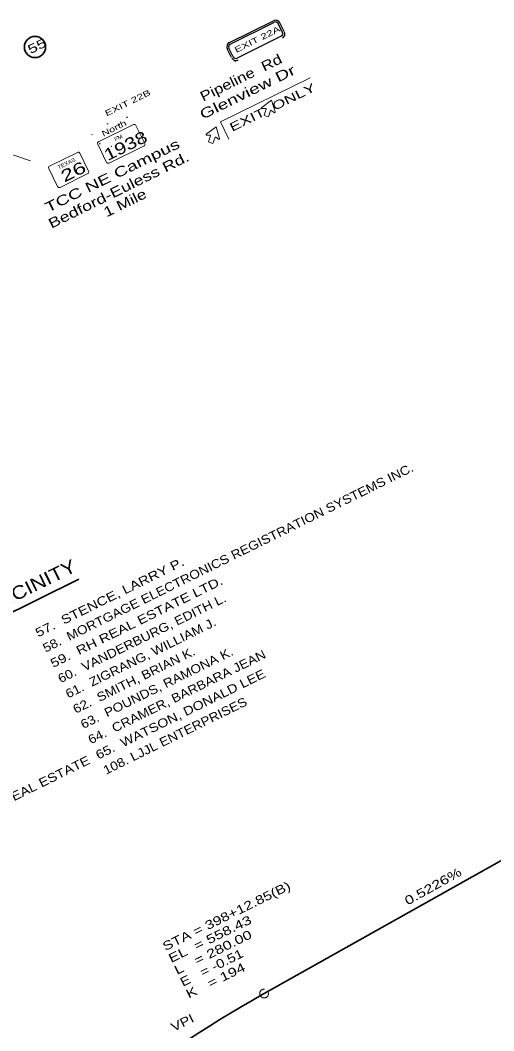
# Model space of a CAD drawing. Extents: x 2356431 to 2371438, y 6972864 to 6982525.
# Drawn here: x 2368116 to 2368867, y 6978894 to 6980496 of the extents above; entities that cross this region are included whole.
import ezdxf
from ezdxf.enums import TextEntityAlignment as Align

# ---------------------------------------------------------------- set-up
doc = ezdxf.new("R2010")
doc.units = 0
doc.header["$LTSCALE"] = 5.6
doc.linetypes.add('LONG_DASH_SHORT_DASH', pattern=[9.9, 6, -1.2, 1.5, -1.2])
for name, color, linetype, lineweight in [('1', 7, 'Continuous', 25), ('17', 7, 'Continuous', 35), ('18', 7, 'Continuous', 35), ('2', 7, 'Continuous', 35), ('37', 7, 'Continuous', 13), ('52', 7, 'Continuous', 25), ('53', 7, 'Continuous', 13), ('61', 7, 'Continuous', 13)]:
    doc.layers.add(name, color=color, linetype=linetype, lineweight=lineweight)

msp = doc.modelspace()

# ---------------------------------------------------------------- linework, layer by layer
at = {"layer": '1'}
for p, q in [((2368448.027, 6980460.496), (2368517.953, 6980495.077)), ((2368449.272, 6980457.976), (2368519.197, 6980492.557)), ((2368532.331, 6980476.581), (2368525.481, 6980490.434)), ((2368534.85, 6980477.825), (2368527.999, 6980491.678)), ((2368530.207, 6980470.299), (2368460.278, 6980435.725)), ((2368451.477, 6980436.604), (2368444.63, 6980450.449)), ((2368453.997, 6980437.848), (2368447.149, 6980451.695))]:
    msp.add_line(p, q, dxfattribs=at)
at = {"layer": '1', "lineweight": 13}
for p, q in [((2367641.836, 6980439.9), (2368132.862, 6980272.956)), ((2368433.917, 6980334.523), (2368576.114, 6980404.665)), ((2368296.138, 6980330.412), (2368240.531, 6980302.908)), ((2368314.058, 6980300.51), (2368299.904, 6980329.13)), ((2368447.341, 6980307.308), (2368433.917, 6980334.523)), ((2368239.257, 6980299.145), (2368253.408, 6980270.522)), ((2368257.176, 6980269.242), (2368312.783, 6980296.746)), ((2368206.997, 6980286.329), (2368162.867, 6980264.511)), ((2368224.923, 6980256.432), (2368210.772, 6980285.054)), ((2368161.594, 6980260.738), (2368175.749, 6980232.119)), ((2368179.513, 6980230.846), (2368223.642, 6980252.663))]:
    msp.add_line(p, q, dxfattribs=at)
at = {"layer": '1'}
for centre, radius, start, end in [((2368521.278, 6980488.351), 7.501, 26.31114, 116.31114), ((2368521.278, 6980488.351), 4.688, 26.31114, 116.31114), ((2368528.127, 6980474.501), 4.688, 296.31114, 26.31114), ((2368528.605, 6980474.193), 7.501, 296.31114, 26.31114), ((2368451.352, 6980453.775), 7.501, 116.31114, 206.31114), ((2368451.352, 6980453.775), 4.688, 116.31114, 206.31114), ((2368458.414, 6980439.494), 7.501, 206.31114, 296.31114), ((2368458.201, 6980439.924), 4.688, 206.31114, 296.31114)]:
    msp.add_arc(centre, radius, start, end, dxfattribs=at)
at = {"layer": '1', "lineweight": 13}
for centre, start, end in [((2368297.383, 6980327.887), 26.31197, 116.31197), ((2368241.775, 6980300.392), 116.31197, 206.31197), ((2368311.537, 6980299.262), 296.31197, 26.31197), ((2368208.248, 6980283.812), 26.31197, 116.31197), ((2368164.11, 6980261.986), 116.31197, 206.31197), ((2368255.93, 6980271.768), 206.31197, 296.31197), ((2368222.403, 6980255.188), 296.31197, 26.31197), ((2368178.265, 6980233.362), 206.31197, 296.31197)]:
    msp.add_arc(centre, 2.813, start, end, dxfattribs=at)
at = {"layer": '17'}
msp.add_line((2367561.881, 6979290.19), (2368209.441, 6979609.782), dxfattribs=at)
msp.add_circle((2368139.838, 6980453.305), 16.828, dxfattribs=at)
at = {"layer": '2'}
msp.add_line((2368502.99, 6978952.713), (2368889.441, 6979169.404), dxfattribs=at)
msp.add_lwpolyline([(2368416.215, 6978901.102), (2368432.996, 6978911.561), (2368449.864, 6978921.839)], dxfattribs=at)
at = {"layer": '37'}
for p, q in [((2368456.29, 6980430.93), (2368458.296, 6980430.928)), ((2368286.243, 6980342.815), (2368284.953, 6980341.276)), ((2368253.695, 6980331.616), (2368255.701, 6980331.614)), ((2368274.488, 6980330.361), (2368272.531, 6980329.953)), ((2368229.406, 6980314.094), (2368231.216, 6980314.922)), ((2368272.078, 6980310.735), (2368270.16, 6980311.283)), ((2368242.065, 6980299.085), (2368243.028, 6980300.837)), ((2368261.295, 6980294.855), (2368260.542, 6980296.699))]:
    msp.add_line(p, q, dxfattribs=at)
at = {"layer": '53'}
for p, q in [((2368499.419, 6980357.66), (2368514.92, 6980368.95)), ((2368505.534, 6980355.921), (2368499.996, 6980355.796)), ((2368514.92, 6980368.95), (2368520.317, 6980350.564)), ((2368518.738, 6980349.446), (2368514.398, 6980352.91)), ((2368417.493, 6980313.542), (2368411.956, 6980313.416)), ((2368425.311, 6980310.234), (2368425.302, 6980310.211)), ((2368430.696, 6980307.067), (2368426.358, 6980310.532))]:
    msp.add_line(p, q, dxfattribs=at)
for points in [[(2368513.343, 6980352.588), (2368510.006, 6980342.757), (2368506.432, 6980343.97), (2368502.851, 6980345.181), (2368506.195, 6980355.02)], [(2368411.379, 6980315.282), (2368426.88, 6980326.571), (2368432.278, 6980308.186)], [(2368425.302, 6980310.211), (2368421.965, 6980300.378), (2368418.392, 6980301.591), (2368414.81, 6980302.803), (2368418.156, 6980312.642)]]:
    msp.add_lwpolyline(points, dxfattribs=at)
at = {"layer": '53', "lineweight": 35}
for points in [[(2368449.864, 6978921.839), (2368466.821, 6978931.939), (2368483.868, 6978941.858), (2368501.003, 6978951.598), (2368502.99, 6978952.713)], [(2368382.921, 6978879.648), (2368399.524, 6978890.465), (2368416.215, 6978901.102)]]:
    msp.add_lwpolyline(points, dxfattribs=at)
at = {"layer": '53'}
for centre, radius, start, end in [((2368499.989, 6980356.82), 1.012, 125.99456, 271.37569), ((2368505.552, 6980355.259), 0.675, 341.25606, 91.23917), ((2368513.99, 6980352.396), 0.675, 51.27296, 161.25606), ((2368519.354, 6980350.249), 1.012, 231.13643, 16.51757), ((2368411.949, 6980314.442), 1.012, 125.99456, 271.37569), ((2368417.512, 6980312.881), 0.675, 341.25606, 91.23917), ((2368425.95, 6980310.017), 0.675, 51.27296, 161.25606), ((2368431.314, 6980307.871), 1.012, 231.13643, 16.51757)]:
    msp.add_arc(centre, radius, start, end, dxfattribs=at)
at = {"layer": '61', "linetype": 'LONG_DASH_SHORT_DASH'}
msp.add_circle((2368502.99, 6978952.713), 7, dxfattribs=at)

# ---------------------------------------------------------------- texts
at = {"layer": '1'}
for s, height, rotation, width, p in [('EXIT 22A', 9.188, 26.311, 1.5, (2368494.197, 6980461.368)), ('Pipeline  Rd', 15.68, 26.256, 1.25, (2368469.821, 6980397.777)), ('Glenview Dr', 15.68, 26.256, 1.45, (2368480.017, 6980374.73)), ('EXIT 22B', 9.188, 26.311, 1.5, (2368288.792, 6980360.664)), ('EXIT  ONLY', 13.5, 26.256, 1.5, (2368519.115, 6980351.77)), ('North', 9.188, 26.311, 1.4, (2368267.166, 6980320.475)), ('TCC NE Campus', 15.68, 26.256, 1.45, (2368265.761, 6980242.56)), ('Bedford-Euless Rd.', 15.68, 26.256, 1.35, (2368275.961, 6980219.512)), ('1 Mile', 15.68, 26.256, 1.3, (2368285.951, 6980199.259))]:
    msp.add_text(s, height=height, rotation=rotation, dxfattribs=dict(at, width=width)).set_placement(p, align=Align.CENTER)
for s, height, width, p in [('1938', 18.75, 1.3, (2368255.07, 6980272.343)), ('FM', 6, 1.15, (2368267.348, 6980303.794)), ('TEXAS', 6, 1.15, (2368177.502, 6980259.364)), ('26', 18.75, 1.45, (2368186.544, 6980238.455))]:
    msp.add_text(s, height=height, rotation=26.312, dxfattribs=dict(at, width=width)).set_placement(p)
at = {"layer": '17', "width": 1.45}
msp.add_text('55', height=14, rotation=26.268, dxfattribs=at).set_placement((2368146.133, 6980448.606), align=Align.CENTER)
at = {"layer": '17', "width": 1.2}
msp.add_text('PROPERTY OWNERS IN  PROJECT VICINITY', height=21, rotation=26.268, dxfattribs=at).set_placement((2367564.429, 6979305.731))
at = {"layer": '18'}
for s, width, p in [('58.  MORTGAGE ELECTRONICS REGISTRATION SYSTEMS INC.', 1.15, (2368156.67, 6979493.108)), ('57.  STENCE, LARRY P. ', 1.25, (2368144.721, 6979517.319)), ('59.  RH REAL ESTATE LTD.', 1.25, (2368168.619, 6979468.896)), ('60.  VANDERBURG, EDITH L.', 1.15, (2368180.569, 6979444.684)), ('61.  ZIGRANG, WILLIAM J.', 1.15, (2368192.518, 6979420.472)), ('62.  SMITH, BRIAN K.', 1.15, (2368204.467, 6979396.26)), ('63.  POUNDS, RAMONA K.', 1.15, (2368216.417, 6979372.048)), ('64.  CRAMER, BARBARA JEAN', 1.15, (2368228.366, 6979347.837)), ('65.  WATSON, DONALD LEE ', 1.2, (2368240.315, 6979323.625)), ('108. LJJL ENTERPRISES', 1.15, (2368252.265, 6979299.413)), ('55.  OMEGA AUTOMOTIVE REAL ESTATE', 1.2, (2367833.366, 6979122.777))]:
    msp.add_text(s, height=14, rotation=26.268, dxfattribs=dict(at, width=width)).set_placement(p)
at = {"layer": '2', "width": 1.35}
msp.add_text('0.5226% ', height=14, rotation=29.259, dxfattribs=at).set_placement((2368730.576, 6979092.236))
at = {"layer": '52'}
for s, width, p in [('STA = 398+12.85(B)', 1.3, (2368346.341, 6979019.919)), ('EL  = 558.43', 1.35, (2368355.634, 6979001.088)), ('L   = 280.00', 1.35, (2368364.928, 6978982.257)), ('E   = -0.51', 1.25, (2368374.222, 6978963.425)), ('K   = 194', 1.35, (2368383.516, 6978944.594))]:
    msp.add_text(s, height=14, rotation=26.268, dxfattribs=dict(at, width=width)).set_placement(p)
at = {"layer": '61', "width": 1.25}
msp.add_text('VPI', height=14, rotation=26.268, dxfattribs=at).set_placement((2368376.611, 6978900.247), align=Align.CENTER)

doc.saveas('drawing.dxf')
